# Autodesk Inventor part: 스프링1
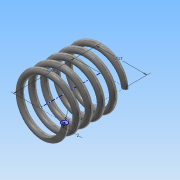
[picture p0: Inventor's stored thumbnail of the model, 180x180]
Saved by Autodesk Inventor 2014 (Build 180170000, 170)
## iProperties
Created: 2016-01
Part Number: 스프링1
Material: 강철, 탄소
Document SubType Name: Modeling
Designer: Administrator
Density: 1 g/cm^3
Appearance: 반연마
Mass: 0.821961 g
Surface Area: 16.7185 cm^2
Volume: 0.821961 cm^3
Author: Administrator
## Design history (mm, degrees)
sketch "스케치1"
  geometry: L1 (0, 0)-(8.5, 0); L2 (8.5, 0)-(8.5, 20.5); L3 (8.5, 20.5)-(0, 20.5); L4 (0, 20.5)-(0, 0); C1 r 1 at (8.5, 0)
  constraints: 8 end point, 2 parallel, 1 centre point, 1 coincident, 1 horizontal, 1 perpendicular
  dimensions: "d0" = 20.5 distance of L3.end L1.start (derived); "d1" = 17 diameter of L2 L4; "d2" = 2 diameter of C1
feature "코일1" pitch "d3" = 10; turns "d5" = 5; dims "d4" = 20.5 (= d0), "d6" = 0, angle "d7" = 90 deg, angle "d8" = 90 deg, "d9" = 0, "d10" = 0
node "작업 평면1"
sketch "스케치2"
  geometry: L1 (7.5, 0)-(9.5, 0) reference; 1 further point
  constraints: 1 horizontal alignment
extrude "돌출1" cut sketch "스케치2" stored distance "d12" = 10; taper "d13" = 0 deg
node "작업 평면2"
sketch "스케치3"
  geometry: L1 (-7.5, 0)-(-9.5, 0) reference; 1 further point
  constraints: 1 horizontal alignment
extrude "돌출2" cut sketch "스케치3" stored distance "d15" = 10; taper "d16" = 0 deg
node "솔리드1"
node "절단 모서리 투영1"
node "절단 모서리 투영2"
other parameters: "d11" = 0, "d14" = 20.5 (= d0)
